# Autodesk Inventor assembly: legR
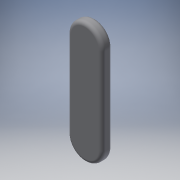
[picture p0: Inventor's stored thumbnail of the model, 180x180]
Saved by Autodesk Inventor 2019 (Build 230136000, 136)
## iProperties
Created: 2020-09
Part Number: legR
Material: 一般
Document SubType Name: Assembly
Designer: kikut
Author: kikut
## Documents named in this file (2)
- F:\openFOAM\basilisk\oversetmeshlegR\CAD\legR.iam
- F:\openFOAM\basilisk\oversetmeshlegR\CAD\leg.ipt
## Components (1 placed, 1 different names)
1. leg:1 — メイト:1, メイト:2
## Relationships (2: Mate 2)
- メイト:1 [Mate]: leg:1
- メイト:2 [Mate]: leg:1
